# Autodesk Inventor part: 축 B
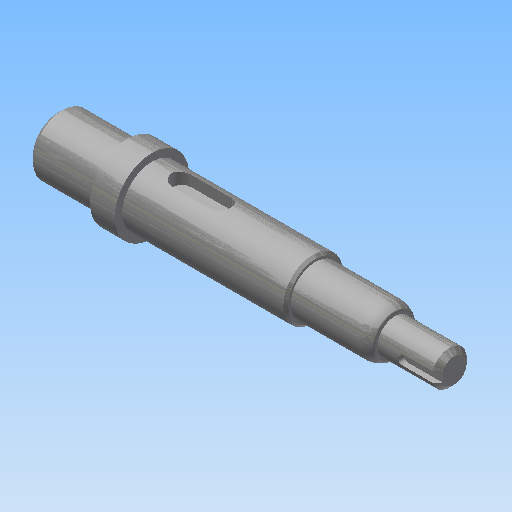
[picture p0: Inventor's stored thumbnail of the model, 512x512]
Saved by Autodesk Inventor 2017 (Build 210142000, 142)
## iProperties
Created: 2020-04
Part Number: 축 B
Material: 강철, 연강
Document SubType Name: Modeling
Designer: mduedu
Density: 7.86 g/cm^3
Mass: 60.8598 g
Surface Area: 31.2859 cm^2
Volume: 7.74298 cm^3
Appearance: 강철
Author: mduedu
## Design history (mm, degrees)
sketch "스케치1"
  geometry: L1 (0, 0)-(14, 0); L2 (14, 0)-(14, 6); L3 (14, 6)-(0, 6); L4 (0, 6)-(0, 0); L5 (14, 0)-(19, 0); L6 (19, 0)-(19, 7.5); L7 (19, 7.5)-(14, 7.5); L8 (14, 7.5)-(14, 0); L9 (19, 0)-(52, 0); L10 (52, 0)-(52, 6); L11 (52, 6)-(19, 6); L12 (19, 6)-(19, 0); L13 (52, 0)-(68, 0); L14 (68, 0)-(68, 5); L15 (68, 5)-(52, 5); L16 (52, 5)-(52, 0); L17 (68, 0)-(80, 0); L18 (80, 0)-(80, 3.5); L19 (80, 3.5)-(68, 3.5); L20 (68, 3.5)-(68, 0)
  constraints: 40 end point, 10 parallel, 5 horizontal, 5 perpendicular
  dimensions: "d0" = 80 distance between parallel lines of L18 L4; "d2" = 14 distance of L2.end L3.end; "d3" = 5 distance of L6.end L7.end; "d5" = 7 diameter of L19 L17; "d6" = 10 diameter of L15 L13; "d7" = 12 diameter of L11 L9; "d8" = 12 diameter of L3 L1; "d9" = 15 diameter of L7 L5; "d35" = 16 distance of L14.end L15.end; "d36" = 52 distance between parallel lines of L10 L4
revolve "회전1" sketch "스케치1" stored, may be unused: angle "d11" = 90 deg
sketch "스케치2"
  geometry: L1 (0, 6)-(0, -6) reference; L2 (0, -6)-(-14, -6) reference; L3 (-14, -6)-(-14, -7.5) reference; L4 (-14, -7.5)-(-19, -7.5) reference; L5 (-19, -7.5)-(-19, -6) reference; L6 (-19, -6)-(-52, -6) reference; L7 (-52, -6)-(-52, -5) reference; L8 (-52, -5)-(-68, -5) reference; L9 (-68, -5)-(-68, -3.5) reference; L10 (-68, -3.5)-(-80, -3.5) reference; L11 (-80, -3.5)-(-80, 3.5) reference; L12 (-80, 3.5)-(-68, 3.5) reference; L13 (-68, 3.5)-(-68, 5) reference; L14 (-68, 5)-(-52, 5) reference; L15 (-52, 5)-(-52, 6) reference; L16 (-52, 6)-(-19, 6) reference; L17 (-19, 6)-(-19, 7.5) reference; L18 (-19, 7.5)-(-14, 7.5) reference; L19 (-14, 7.5)-(-14, 6) reference; L20 (-14, 6)-(0, 6) reference; L21 (-80, 3.5)-(-72, 3.5); L22 (-72, 3.5)-(-72, 2.3); L23 (-72, 2.3)-(-80, 2.3); L24 (-80, 2.3)-(-80, 3.5); 1 further point
  constraints: 8 end point, 2 parallel, 1 horizontal, 1 perpendicular
  dimensions: "d37" = 8 distance of L22.end L23.end; "d38" = 1.2 distance of L21.end L22.end
extrude "돌출1" cut sketch "스케치2" stored distance "d14" = 2; taper "d15" = 0 deg
fillet "모깎기1" dims "d16" = 1
sketch "스케치3"
  geometry: L1 (0, -6)-(0, 6) reference; L2 (0, 6)-(14, 6) reference; L3 (14, 6)-(14, 7.5) reference; L4 (14, 7.5)-(19, 7.5) reference; L5 (19, 7.5)-(19, 6) reference; L6 (19, 6)-(52, 6) reference; L7 (52, 6)-(52, 5) reference; L8 (52, 5)-(68, 5) reference; L9 (68, 5)-(68, 3.5) reference; L10 (68, 3.5)-(80, 3.5) reference; L11 (80, 3.5)-(80, -3.5) reference; L12 (80, -3.5)-(68, -3.5) reference; L13 (68, -3.5)-(68, -5) reference; L14 (68, -5)-(52, -5) reference; L15 (52, -5)-(52, -6) reference; L16 (52, -6)-(19, -6) reference; L17 (19, -6)-(19, -7.5) reference; L18 (19, -7.5)-(14, -7.5) reference; L19 (14, -7.5)-(14, -6) reference; L20 (14, -6)-(0, -6) reference; L21 (23, 6)-(35, 6); L22 (35, 6)-(35, 3.5); L23 (35, 3.5)-(23, 3.5); L24 (23, 3.5)-(23, 6); 1 further point
  constraints: 8 end point, 2 parallel, 1 horizontal, 1 perpendicular, 1 point on line
  dimensions: "d17" = 12 distance of L22.end L23.end; "d18" = 2.5 distance of L21.end L22.end; "d19" = 4 distance from line of L24 L4.end
extrude "돌출2" cut sketch "스케치3" stored distance "d20" = 4; taper "d21" = 0 deg
fillet "모깎기2" dims "d22" = 2
chamfer "모따기1" distance "d23" = 1; stored, may be unused: second distance "d24" = 2, angle "d25" = 45 deg
chamfer "모따기2" distance "d26" = 0.5; stored, may be unused: second distance "d27" = 2, angle "d28" = 45 deg
fillet "모깎기3" dims "d29" = 0.3
chamfer "모따기3" distance "d30" = 1.39; stored, may be unused: second distance "d31" = 2, angle "d32" = 30 deg
fillet "모깎기4" dims "d33" = 4, "d34" = 0.5
node "솔리드1"
node "절단 모서리 투영2"
node "절단 모서리 투영3"
